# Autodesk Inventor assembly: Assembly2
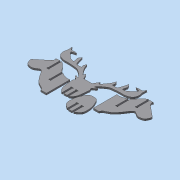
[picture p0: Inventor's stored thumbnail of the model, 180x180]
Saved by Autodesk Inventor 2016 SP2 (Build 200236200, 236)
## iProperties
Created: 2017-07
Part Number: Assembly2
Document SubType Name: Assembly
Designer: Mohamed A.
Author: Mohamed A.
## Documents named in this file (4)
- C:\Users\Mohamed\Documents\inventor\cam\Assembly2.iam
- C:\Users\Mohamed\Documents\inventor\cam\Part1.ipt
- C:\Users\Mohamed\Documents\inventor\cam\Part3.ipt
- C:\Users\Mohamed\Documents\inventor\cam\Part2.ipt
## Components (4 placed, 3 different names)
1. Part1:1 — Flush:1, Flush:2, Flush:3
2. Part3:1 — Flush:2
3. Part3:2 — Flush:3
4. Part2:1 — Flush:1
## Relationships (3: Flush 3)
- Flush:1: Part1:1 ↔ Part2:1
- Flush:2: Part1:1 ↔ Part3:1
- Flush:3: Part1:1 ↔ Part3:2
